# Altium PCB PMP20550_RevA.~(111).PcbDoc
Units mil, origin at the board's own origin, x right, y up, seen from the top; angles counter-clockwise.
Board outline 1966.66 x 1968.77 mil, 4 copper layers (Top Layer, POWER, GNDS, Bottom Layer), stack 79.834 mil thick; 56 components, 23 nets, 134 pads, 84 vias.
Unrouted connection lines stored in the file: 1.
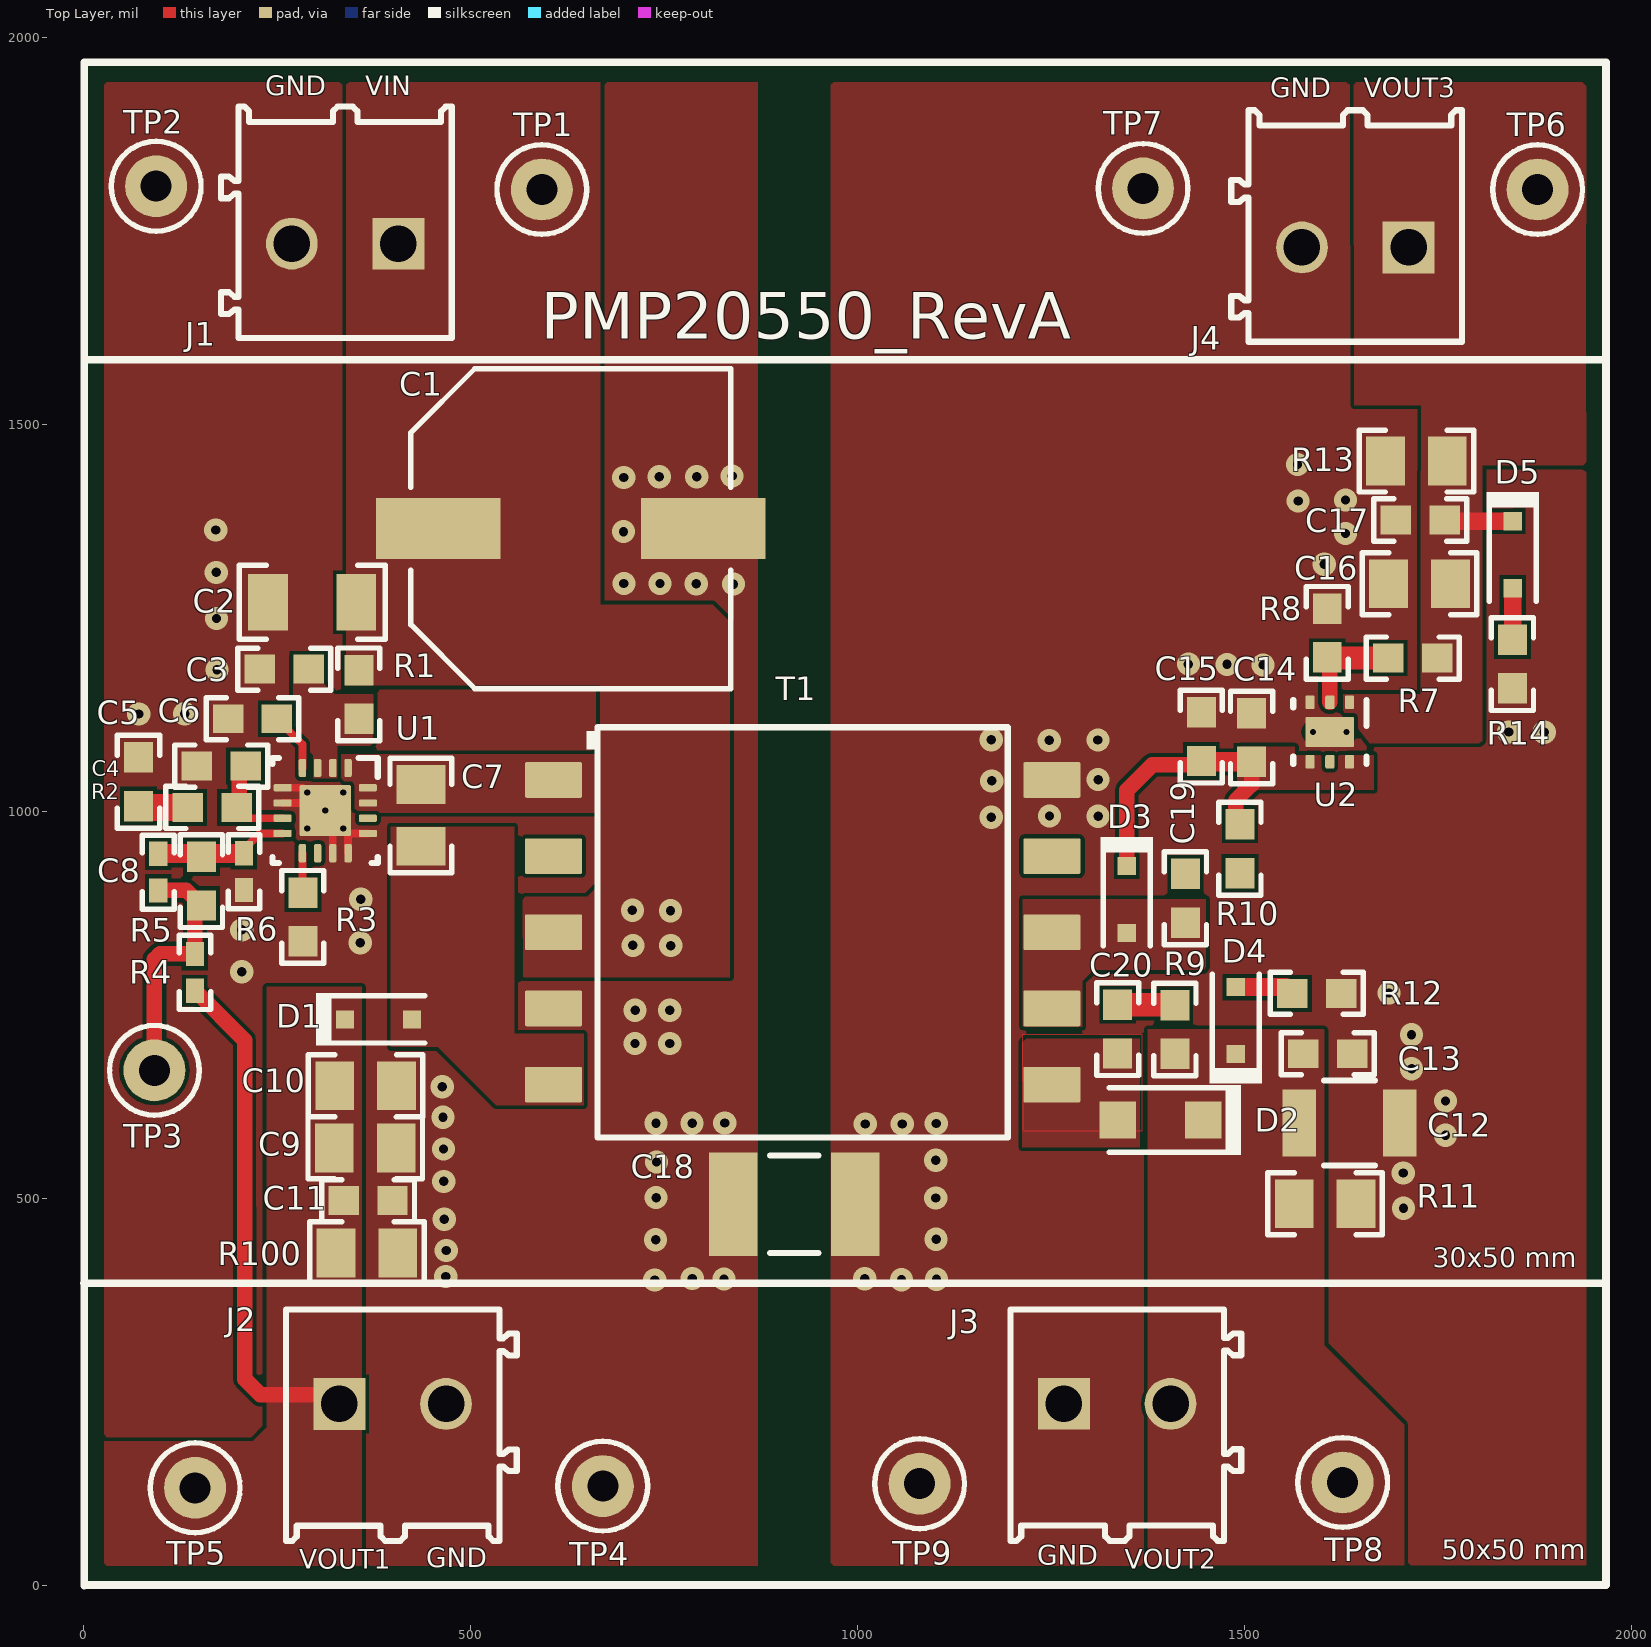
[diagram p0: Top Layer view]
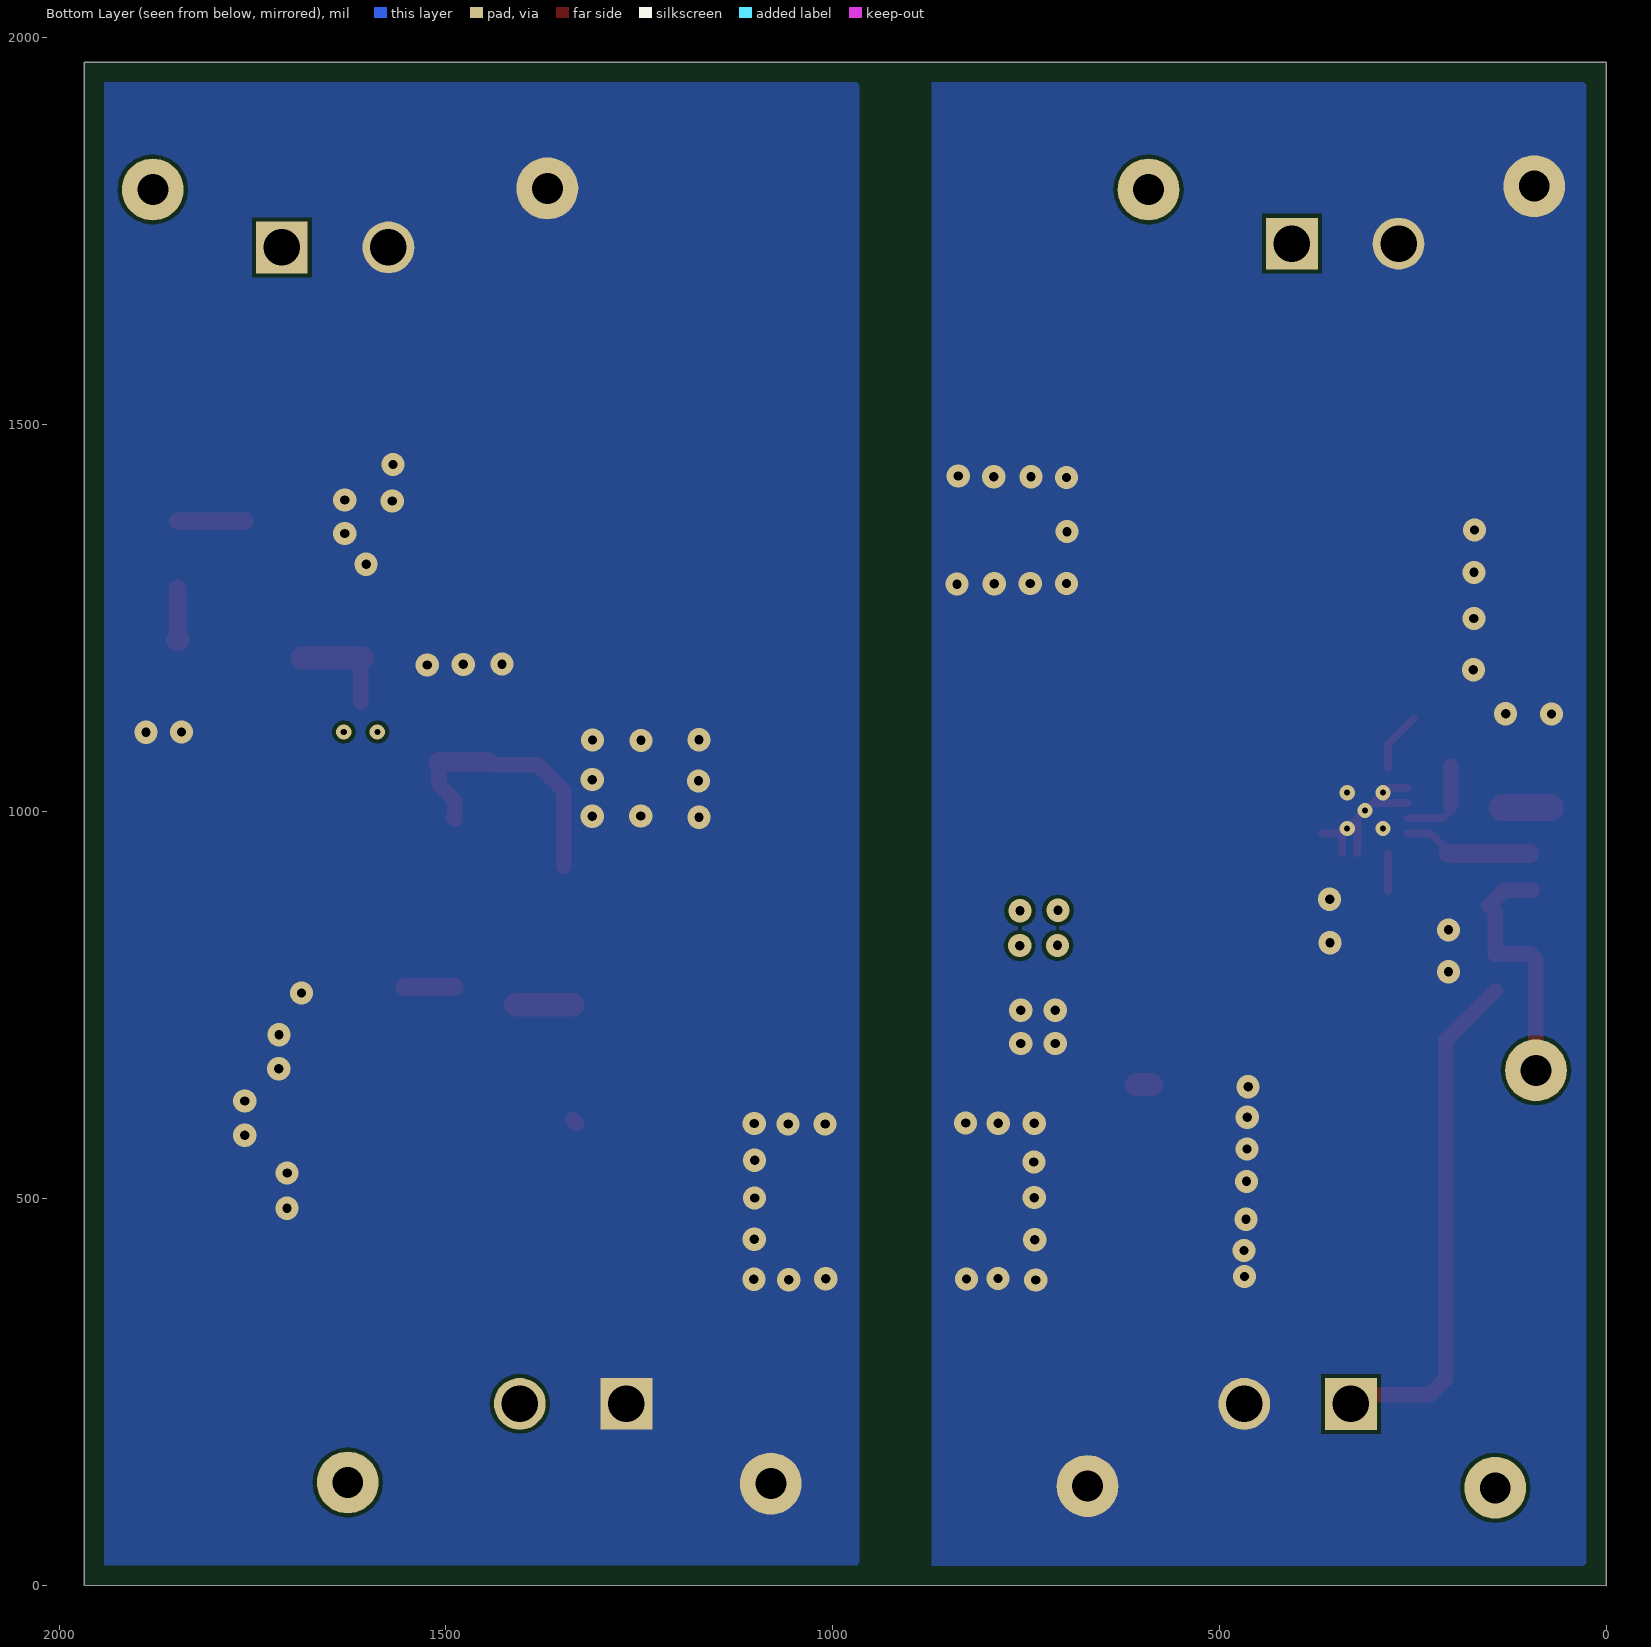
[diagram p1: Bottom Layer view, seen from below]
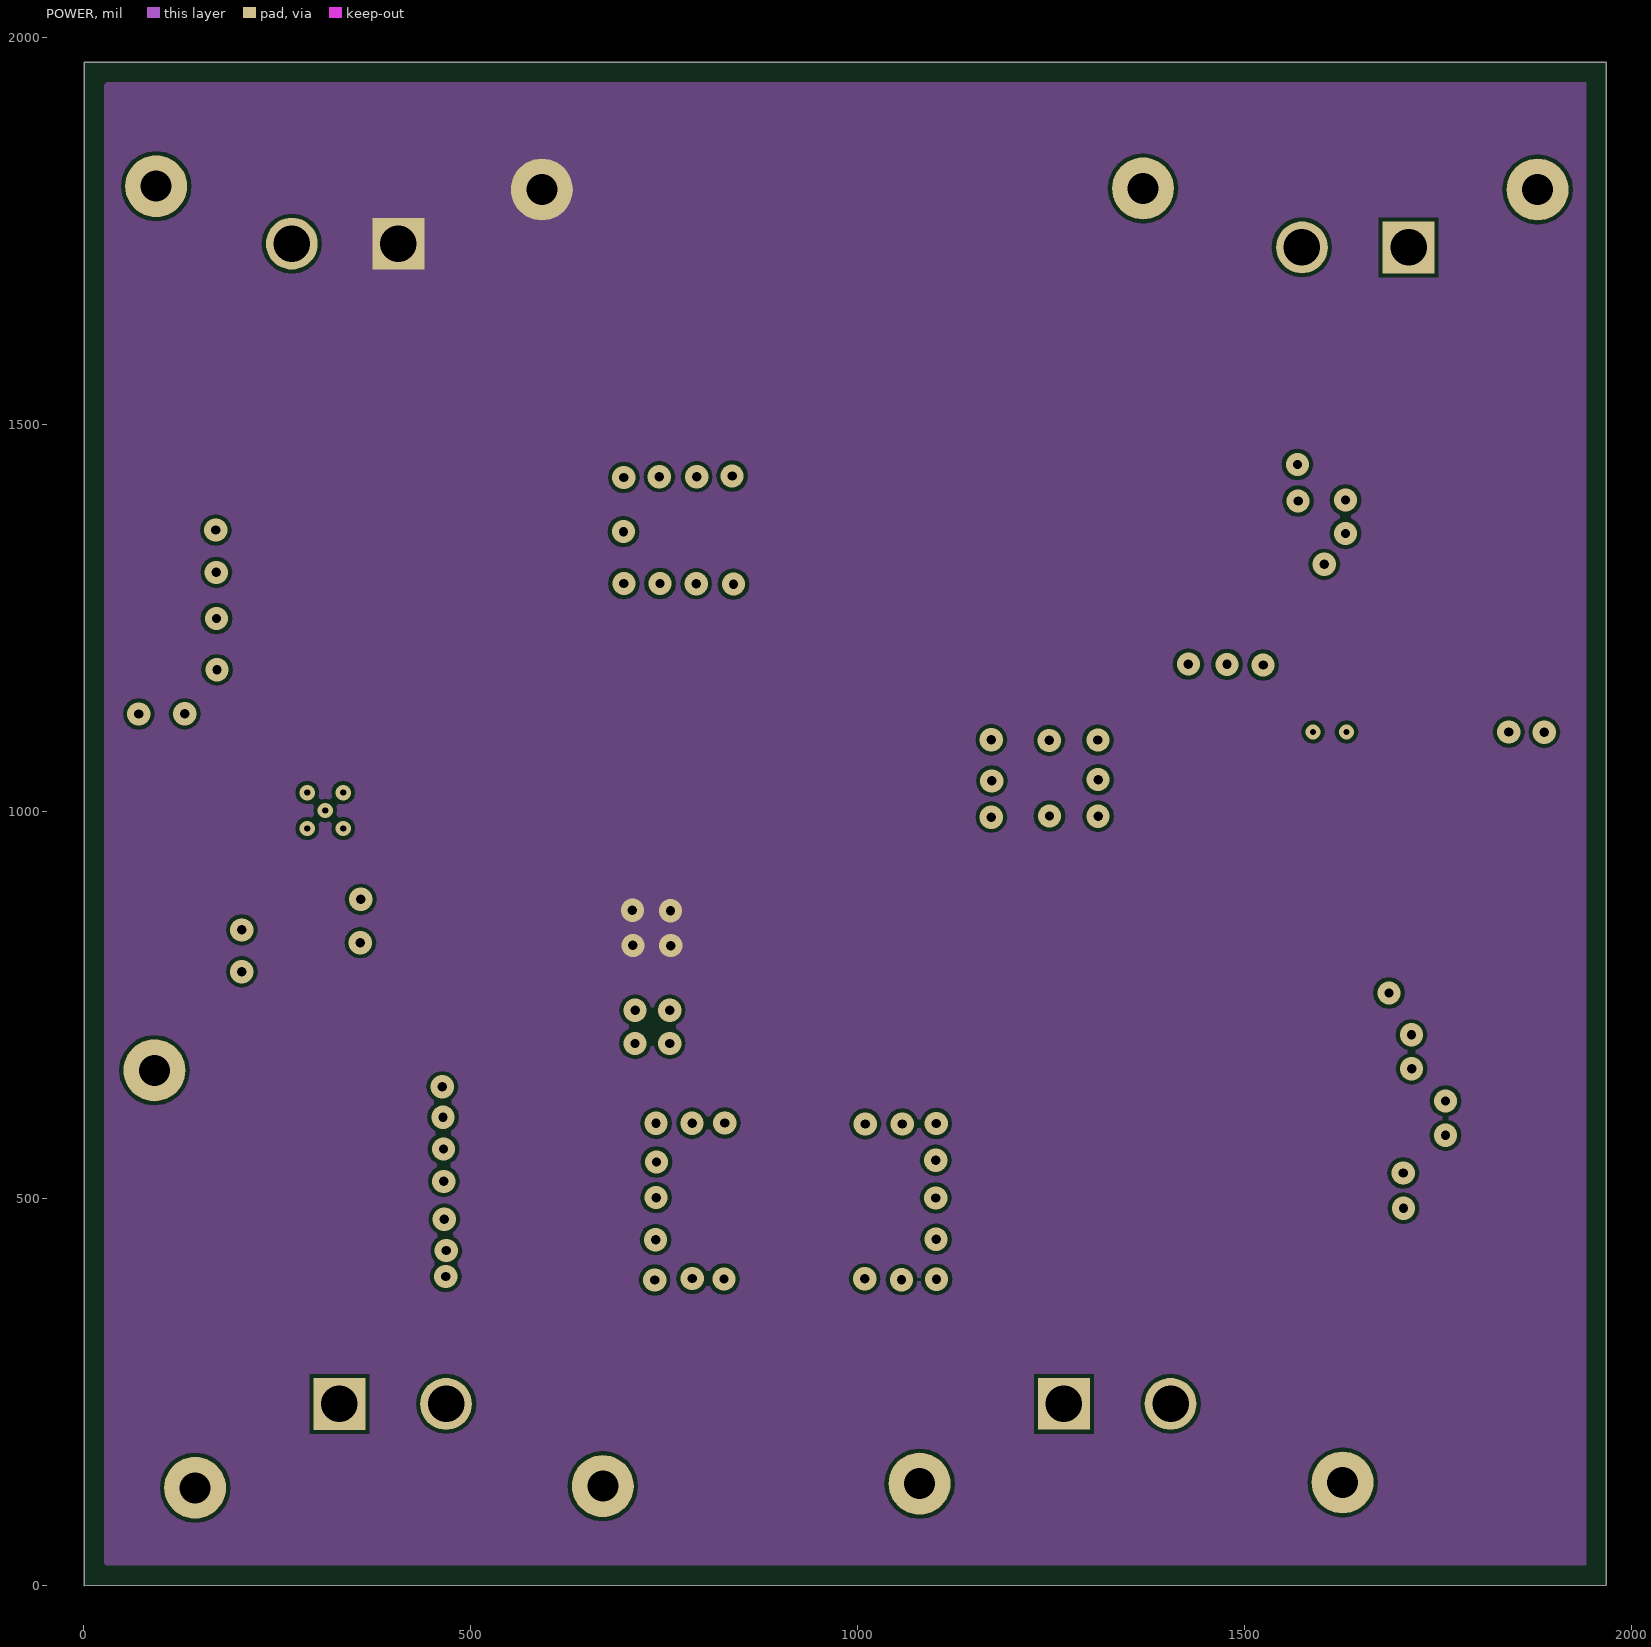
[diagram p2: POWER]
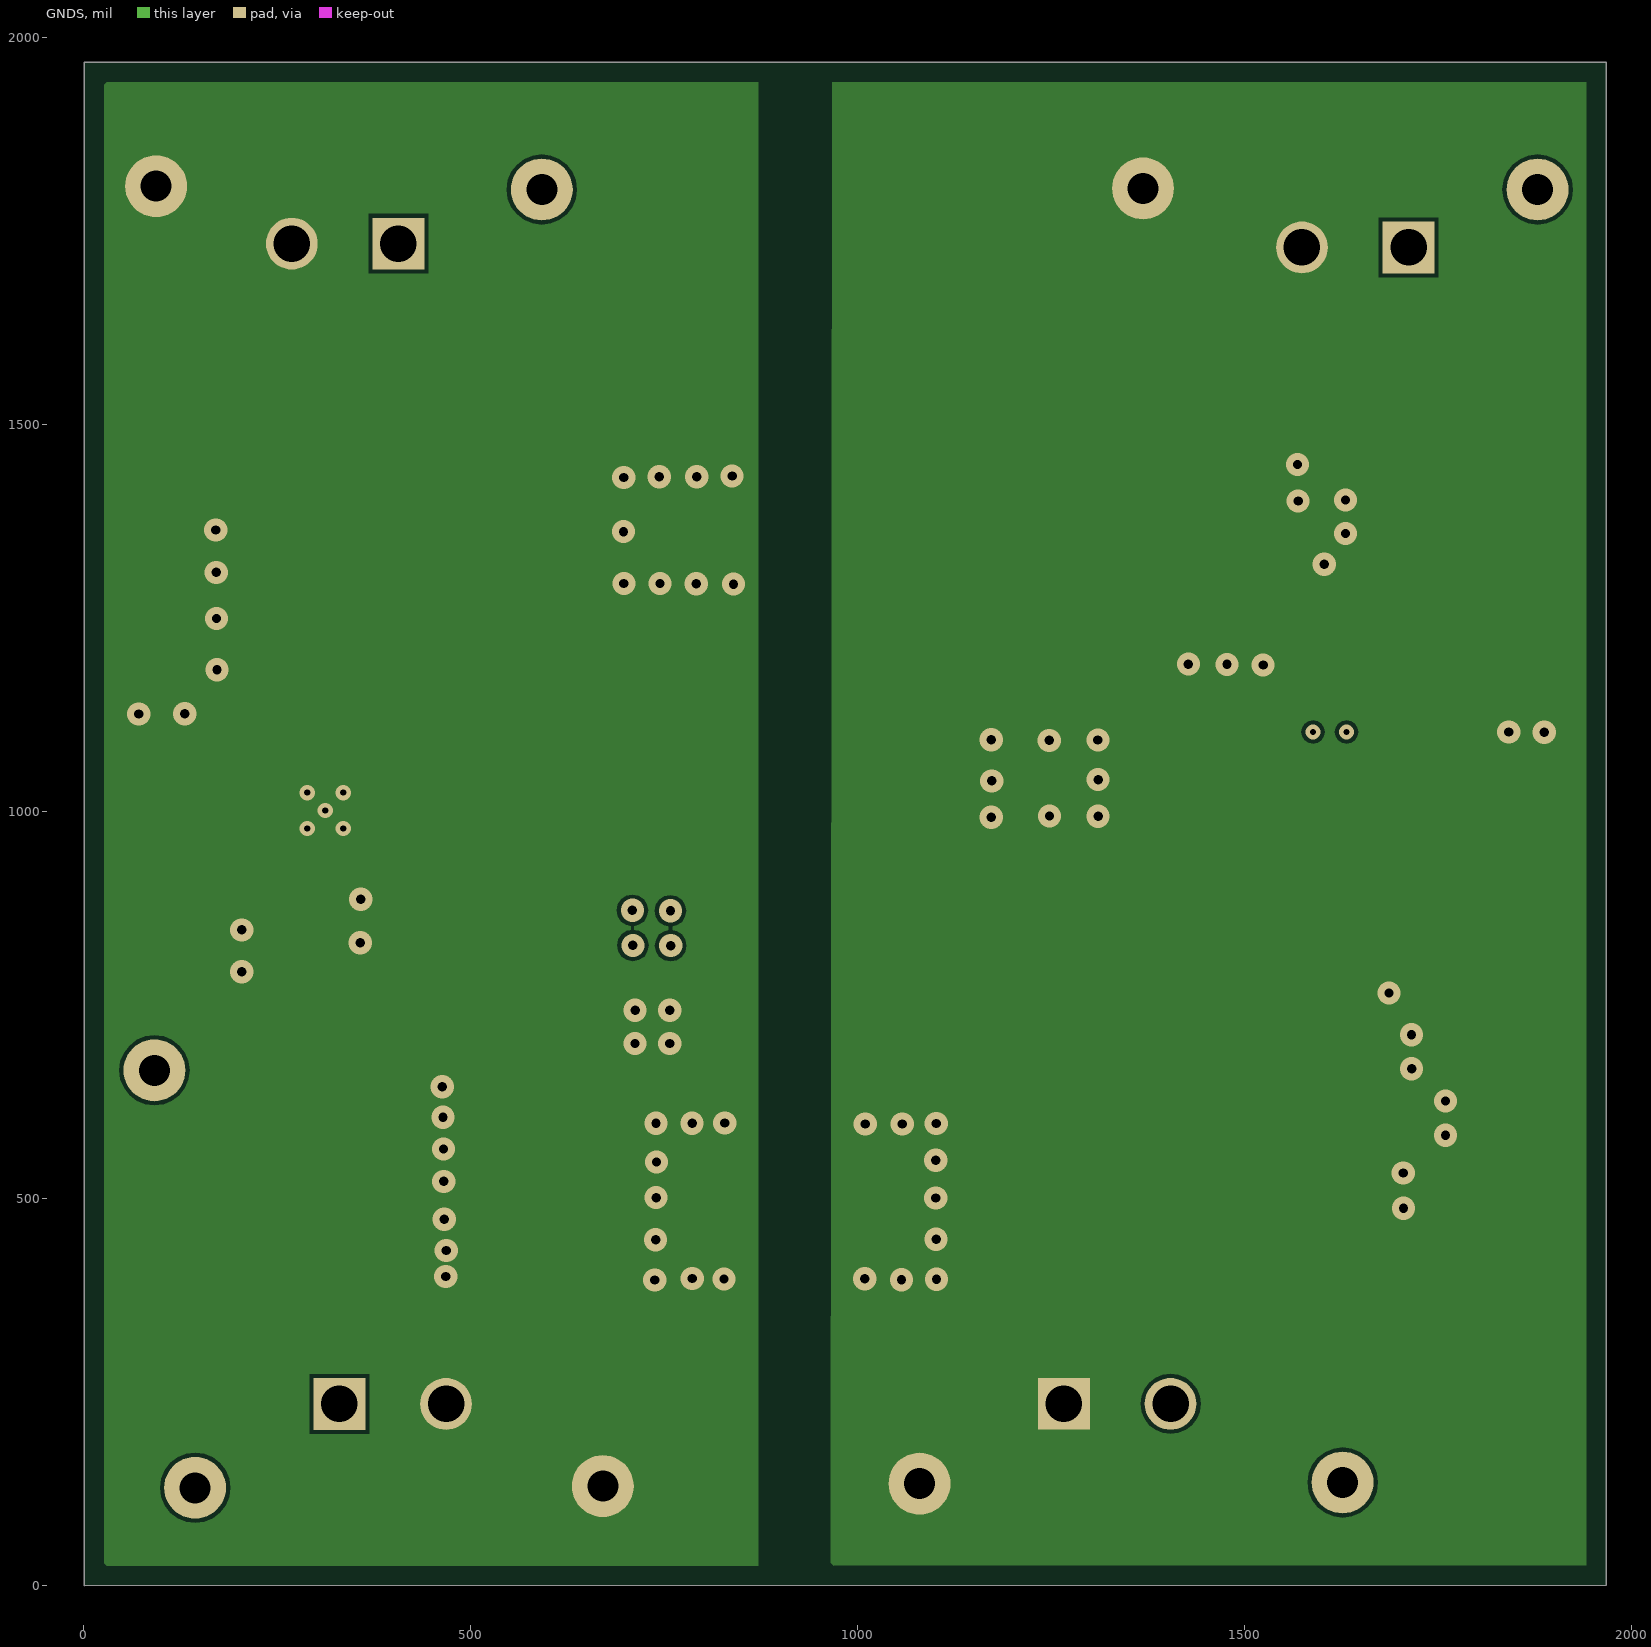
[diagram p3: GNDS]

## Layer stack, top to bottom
Top Solder: solder mask 0.4, Solder Resist, Dk 3.5
Top Layer: signal copper 1.4
Dielectric1: core 59.2, FR-4, Dk 4.8
POWER: signal copper 1.417
Dielectric 3: prepreg 5, Dk 4.2
GNDS: signal copper 1.417
Dielectric 2: core 10, Dk 4.2
Bottom Layer: signal copper 1.4
Bottom Solder: solder mask 0.4, Solder Resist, Dk 3.5

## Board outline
0.76,-0.43 0.76,1968.34 0.81,1968.29 1967.33,1968.29 1967.42,1968.2 1967.42,0.32 1967.36,0.38

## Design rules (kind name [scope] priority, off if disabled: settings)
AcuteAngle [All] p1: minimum=4.50000000000000E+0001 checktracksonly=FALSE
AssemblyTestPointUsage [All] p1: valid=2
BoardOutlineClearance BoardOutlineClearance_MountingHoles [OnCopper and InComponentClass('Mounting Holes')] p1: gap=40
BoardOutlineClearance BoardOutlineClearance_Poly [OnCopper and IsPoly] p2: gap=25
BoardOutlineClearance [OnCopper and Not InComponentClass('Logo') and not InComponentClass('FiducialMark') and not InRegion(1000,500,4000,800) and not InPoly] p3: gap=40
Clearance Clearance_3 [All] p1: gap=5
Clearance Clearance_2 [InNet('NetC1_1') vs InNetClass('Undefined')] p2: gap=80
Clearance Clearance_1 [InNet('GND') vs InNet('GND2')] p3: gap=80
Clearance Clearance_Keepouts [((IsTrack Or IsArc) And Not InPoly) And IsFree and IsKeepOut vs ((IsTrack Or IsArc) And Not InPoly) And IsFree and IsKeepOut] p4: gap=0
Clearance Clearance_Poly [InPolygon] p5: gap=10
Clearance [InNet('GND2') vs InNet('GND2')] p6: gap=0
ComponentClearance ComponentClearance_MountingHoles_FiducialMarks [InComponentClass('Mounting Holes') vs InComponentClass('FiducialMark')] p1: gap=50 collisioncheckmode=3 verticalgap=10 showdistances=FALSE
ComponentClearance ComponentClearance_Shunt [InComponentClass('Header') vs InComponentClass('Shunt')] p2: gap=0 collisioncheckmode=3 verticalgap=0 showdistances=FALSE
ComponentClearance ComponentClearance_Logo [InComponentClass('Logo')] p3: gap=50 collisioncheckmode=3 verticalgap=10 showdistances=FALSE
ComponentClearance ComponentClearance_ScrewToNut [(HasFootprint('NY PMS 440 0025 PH')) vs (HasFootprint('Keystone_1902C'))] p4: gap=5 collisioncheckmode=3 verticalgap=10 showdistances=FALSE
ComponentClearance ComponentClearance_MountingHoles [InComponentClass('Mounting Holes')] p5: gap=250 collisioncheckmode=3 verticalgap=100000 showdistances=FALSE
ComponentClearance ComponentClearance_SmallPassives [HasFootprint('0201*') or HasFootprint('0402*') or HasFootprint('0508') or HasFootprint('0603*') or HasFootprint('0612') or HasFootprint('0805*') or HasFootprint('0815*') or HasFootprint('0830*') or HasFootprint('1206*') or HasFootprint('1210*') or HasFootprint('1808*') or HasFootprint('1812*') or HasFootprint('1825*') or HasFootprint('2010*') or HasFootprint('2220*') or HasFootprint('2225*') or HasFootprint('2512*') or HasFootprint('2728*') or HasFootprint('3518*') vs HasFootprint('0201*') or HasFootprint('0402*') or HasFootprint('0508') or HasFootprint('0603*') or HasFootprint('0612') or HasFootprint('0805*') or HasFootprint('0815*') or HasFootprint('0830*') or HasFootprint('1206*') or HasFootprint('1210*') or HasFootprint('1808*') or HasFootprint('1812*') or HasFootprint('1825*') or HasFootprint('2010*') or HasFootprint('2220*') or HasFootprint('2225*') or HasFootprint('2512*') or HasFootprint('2728*') or HasFootprint('3518*')] p6: gap=14.96 collisioncheckmode=3 verticalgap=10 showdistances=FALSE
ComponentClearance ComponentClearance_THtoSMT [IsThruComponent vs IsSMTComponent] p7: gap=40 collisioncheckmode=3 verticalgap=30 showdistances=FALSE
ComponentClearance ComponentClearance_THtoTH [IsThruComponent vs IsThruComponent] p8: gap=30 collisioncheckmode=3 verticalgap=30 showdistances=FALSE
ComponentClearance [All] p9: gap=30 collisioncheckmode=3 verticalgap=10 showdistances=FALSE
DiffPairsRouting [All] p1: maxlimit=100 minlimit=10 mostfreqgap=10 toplayer_minwidth=15 toplayer_maxwidth=15 toplayer_prefwidth=15 midlayer1_minwidth=15 midlayer1_maxwidth=15 midlayer1_prefwidth=15 midlayer2_minwidth=15 midlayer2_maxwidth=15 midlayer2_prefwidth=15 bottomlayer_minwidth=15 bottomlayer_maxwidth=15 bottomlayer_prefwidth=15 maxuncoupledlength=1000
FabricationTestPointUsage TestPointUsage [All] p1: valid=2 allowmultiple=FALSE
FabricationTestpoint Testpoint [All] p1: side=3 testpointundercomponent=TRUE minsize=40 maxsize=100 preferedsize=60 minholesize=0 maxholesize=40 preferedholesize=32 testpointgrid=1 allowsidetop=TRUE allowsidebottom=TRUE usegrid=TRUE gridtolerance=0.01
FanoutControl Fanout_LCC [IsLCC] p1: bgadir=Out bgaviamode=Centered fanoutstyle=Auto fanoutdirection=Alternating viagrid=1 // Fanout_LCC (Default Rule)
FanoutControl Fanout_BGA [IsBGA] p2: bgadir=Out bgaviamode=Centered fanoutstyle=Auto fanoutdirection=Alternating viagrid=1 // Fanout_BGA (Default Rule)
FanoutControl Fanout_Default [All] p4: bgadir=Out bgaviamode=Centered fanoutstyle=Auto fanoutdirection=Alternating viagrid=1 // Fanout_Default (Default Rule)
FanoutControl Fanout_Small [(CompPinCount < 5)] p5: bgadir=Out bgaviamode=Centered fanoutstyle=Auto fanoutdirection=OutThenIn viagrid=1 // Fanout_Small (Default Rule)
HoleSize [All] p1: absolutevalues=TRUE maxlimit=251 minlimit=7.87 maxpercent=80.000 minpercent=20.000
MinimumAnnularRing MinimumAnnularRing_ThermalPadVias [IsVia and InAnyComponent] p1: minimumring=5.91
MinimumAnnularRing [All] p2: minimumring=8
MinimumSolderMaskSliver MinimumSolderMaskSliver_Logo [InComponentClass('Logo') vs InComponentClass('Logo')] p1: minsoldermaskwidth=0.7
MinimumSolderMaskSliver [All] p2: minsoldermaskwidth=3.94
PlaneConnect [All] p1: planeconnectstyle=Direct reliefexpansion=10 reliefentries=4 reliefconductorwidth=10 reliefairgap=10
PolygonConnect [All] p1: connectstyle=Direct reliefconductorwidth=10 reliefentries=4 polygonreliefangle="90 Angle" airgapwidth=10
RoutingVias ThermalPadVias [IsVia and InAnyComponent] p1: holewidth=7.87 width=19.68 viastyle="Through Hole" minholewidth=7.87 minwidth=19.68 maxholewidth=12.99 maxwidth=23.62
RoutingVias [All] p2: holewidth=16 width=34 viastyle="Through Hole" minholewidth=7.87 minwidth=26 maxholewidth=40 maxwidth=65
SilkToBoardRegionClearance [Not ((IsComment or IsDesignator) And (Hide <> 'False')) and not InRegion(1000,500,4000,800)] p1:
SilkToSilkClearance SilkToSilkClearance_Pb-FreeLogo [(HasFootprint('Pb-Free_Overlay_Medium') OR HasFootprint('Pb-Free_Overlay_Small')) vs (HasFootprint('Pb-Free_Overlay_Medium') OR HasFootprint('Pb-Free_Overlay_Small'))] p1: silktosilkclearance=0
SilkToSilkClearance [All] p2: silktosilkclearance=0
SilkToSolderMaskClearance SilkToComponentPadClearance [IsPad and InAnycomponent] p1: minsilkscreentomaskgap=4 clearancetoexposedcopper=TRUE
SilkToSolderMaskClearance "Silk to Solder Mask Opening" [All] p2: minsilkscreentomaskgap=0 clearancetoexposedcopper=FALSE
SolderMaskExpansion [All] p1: expansion=1.97
Width [All] p1: maxlimit=100 minlimit=6 preferedwidth=10 checkconnectedcopper=TRUE
15 further rules are at their usual default settings.

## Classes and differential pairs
net class Undefined: GND2 NetC12_1 NetC14_1 NetC16_1 NetC19_1 NetC20_1 NetC20_2 NetD4_2 NetD5_2 NetR7_1

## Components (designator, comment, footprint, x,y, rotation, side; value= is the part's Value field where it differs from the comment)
C1 "EEE-FC1V221P" SM_RADIAL_G 629.36,1365.64 r0 top
C2 "GMK316AB7106KL" 1206 295.27,1270.61 r180 top
C3 "C1608X7R1E104K080AA" 0603 259.1,1184.09 r180 top
C4 "CGA3E2NP01H101J080AA" 0603 177.65,1058.89 r180 top
C5 "UMK107AB7105KA-T" 0603 70.82,1038.63 r90 top
C6 "C1608X7R1E104K080AA" 0603 218.14,1119.95 r180 top
C7 "GRM21BR6YA106KE43L" 0805_HV 435.84,995.13 r90 top
C8 "GRM1555C1H201JA01D" 0402 96.31,921.67 r90 top
C9 "GRM21BZ71A226ME15L" 0805_HV 363.79,565.25 r0 top
C10 "GRM21BZ71A226ME15L" 0805_HV 364.32,645.64 r0 top
C11 "C0603X104K8RACTU" 0603 367.54,497.19 r0 top
C12 "12103D226MAT2A" 1210_280 1635.8,597.58 r0 top
C13 "GRM188R71H104KA93D" 0603 1607.68,687.06 r0 top
C14 "GRM188Z71A106MA73D" 0603 1509.32,1095.78 r90 top
C15 "C1608X7R1E104K080AA" 0603 1444.34,1096.88 r90 top
C16 "C2012X7R1E474K125AA" 0805_HV 1726.38,1294.41 r180 top
C17 "C0603X104K8RACTU" 0603 1727.27,1376.89 r180 top
C18 "GR443QR73D102KW01L" 1812 918.24,492.28 r180 top
C19 "GRM1885C1H182JA01D" 0603 1423.82,887.88 r270 top
C20 "GRM1885C1H111JA01D" 0603 1336.26,718.86 r270 top
D1 "PMEG2020EJ,115" SOD-323F 380.91,731.37 r0 top
D2 "PMEG10020ELRX" SOD-123W 1391.56,601.44 r180 top
D3 "PMEG2020EJ,115" SOD-323F 1348.01,886.28 r270 top
D4 "MMSZ5235BS-7-F" SOD-323 1488.8,729.89 r90 top
D5 "MMSZ5235BS-7-F" SOD-323 1846.77,1332.01 r270 top
J1 "1984617" Phoenix_1984617 337.81,1733.95 r180 top
J2 "1984617" Phoenix_1984617 399.35,234.48 r0 top
J3 "1984617" Phoenix_1984617 1335.67,234.61 r0 top
J4 "1984617" Phoenix_1984617 1643.31,1729.21 r180 top
R1 "ERJ-3GEY0R00V" 0603 355.63,1151.46 r90 top
R2 "RT0603BRB071KL" 0603 165.98,1005.32 r0 top
R3 "CRCW0603162KFKEA" 0603 283.22,863.89 r90 top
R4 "ERJ-2RKF49R9X" 0402 143.75,792.24 r270 top
R5 "CRCW060330K9FKEA" 0603 152.08,910.13 r270 top
R6 "ERJ-2RKF1002X" 0402 207.01,922.32 r90 top
R7 "RC0603FR-0778K7L" 0603 1717.69,1198.41 r0 top
R8 "RT0603DRE0724K3L" 0603 1607.13,1230.9 r270 top
R9 "CPF0603B1K62E" 0603 1410.31,718.37 r90 top
R10 "CRCW060340R2FKEA" 0603 1494.28,951.96 r90 top
R11 "ERJ-6ENF4871V" 0805_HV 1604.27,493.15 r180 top
R12 "CPF0603B1K62E" 0603 1593.62,765.04 r0 top
R13 "RT0805BRD071KL" 0805_HV 1722.29,1453.08 r0 top
R14 "CPF0603B1K62E" 0603 1846.38,1190.67 r270 top
R100 "RT0805BRD07499RL" 0805_HV 365.93,429.66 r180 top
T1 "750316553_Rev01" Wurth_750316553 929.2,844.01 r0 top
TP1 "5000" Keystone5000 592.04,1803.94 r90 top
TP2 "5001" Keystone5001 93.57,1808.22 r90 top
TP3 "5003" Keystone5003 91.35,665.59 r0 top
TP4 "5001" Keystone5001 670.84,128.24 r90 top
TP5 "VBUS" Keystone5000 143.95,126.09 r90 top
TP6 "5000" Keystone5000 1878.95,1803.95 r0 top
TP7 "5001" Keystone5001 1369.04,1805.37 r90 top
TP8 "5000" Keystone5000 1627,132.97 r0 top
TP9 "5001" Keystone5001 1080.24,131.4 r0 top
U1 "TPS55340QRTERQ1" RTE0016C 312.12,1001.24 r270 top
U2 "TPS79901QDRVRQ1" DRV0006A 1610.43,1102.85 r270 top

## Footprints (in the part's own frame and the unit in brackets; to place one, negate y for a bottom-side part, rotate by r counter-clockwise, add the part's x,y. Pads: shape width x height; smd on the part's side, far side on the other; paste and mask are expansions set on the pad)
0402 [mm] "0402 from SM-752 data"
  rect 0.8x0.6 smd: 1(-0.6,0) 2(0.6,0)
  silkscreen extent -1.22,-0.52 1.22,0.52, body extent -0.55,-0.3 0.55,0.3, height 0.6
0603 [mm] "0603 from SM-752 data"
  rect 1x0.95 smd: 1(-0.8,0) 2(0.8,0)
  silkscreen extent -1.52,-0.69 1.52,0.69, body extent -0.87,-0.47 0.87,0.47, height 1
0805_HV [mil] "0805 with 30mil clearance between pads"
  rect 50x63 smd: 1(-40,0) 2(40,0)
  silkscreen extent -74,-40 74,40, body extent -43,-29 43,29, height 57
1206 [mm] "1206 from SM-752 data"
  rect 1.3x1.85 smd: 1(-1.45,0) 2(1.45,0)
  silkscreen extent -2.4,-1.21 2.4,1.21, body extent -1.7,-0.9 1.7,0.9, height 1.35
1210_280 [mm] "SMD, 2-Leads, Body 3.6x2.8mm, Height 2.8mm"
  rect 1.1x2.2 smd: 1(-1.65,0) 2(1.65,0)
  silkscreen extent -0.84,-1.4 0.84,1.4, body extent -1.8,-1.4 1.8,1.4, height 2.8
1812 [mm]
  rect 1.6x3.4 smd: 1(-2,0) 2(2,0)
  silkscreen extent -0.8,-1.6 0.8,1.6, body extent -2.4,-1.7 2.4,1.7, height 1.35
DRV0006A [mm] "SON, 6-Leads, Body 2x2mm, Pitch 0.65mm, Thermal Pad 1.6x1mm, TI Recommended"
  rrect33% 0.45x0.3 smd: 1(-0.975,0.65) 2(-0.975,0) 3(-0.975,-0.65) 4(0.975,-0.65) 5(0.975,0) 6(0.975,0.65)
  rrect14% 1x0.7 on Top Paste: 7(0,0.45) 7(0,-0.45)
  rrect10% 1x1.6 smd paste-0.5: 7(0,0)
  silkscreen extent -1.05,-1.2 1.05,1.2, body extent -1.05,-1.05 1.05,1.05, height 0.81
Keystone5000 [mil] "For Keystone 500x miniature loop terminals"
  round 80 hole 40: 1(0,0)
  silkscreen extent -58,-58 58,58, body extent -49,-49 49,49, height 182
Keystone5001 [mil] "For Keystone 500x miniature loop terminals"
  round 80 hole 40: 1(0,0)
  silkscreen extent -58,-58 58,58, body extent -49,-49 49,49, height 182
Keystone5003 [mil] "For Keystone 500x miniature loop terminals"
  round 80 hole 40: 1(0,0)
  silkscreen extent -58,-58 58,58, body extent -49,-49 49,49, height 182
Phoenix_1984617 [mm] "Terminal Block, 3.5mm, 2x1, TH"
  rect 1.7x1.7 hole 1.2: 1(-1.75,0)
  round 1.7 hole 1.2: 2(1.75,0)
  silkscreen extent -3.5,-4.5 4.07,3.1, body extent -3.5,-4.5 4.07,3.1, height 9
RTE0016C [mm] "Texas Insturments"
  rrect42% 0.6x0.24 smd: 1(-1.4,0.75) 2(-1.4,0.25) 3(-1.4,-0.25) 4(-1.4,-0.75) 9(1.4,-0.75) 10(1.4,-0.25) 11(1.4,0.25) 12(1.4,0.75)
  rrect42% 0.24x0.6 smd: 5(-0.75,-1.4) 6(-0.25,-1.4) 7(0.25,-1.4) 8(0.75,-1.4) 13(0.75,1.4) 14(0.25,1.4) 15(-0.25,1.4) 16(-0.75,1.4)
  rrect6% 1.55x1.55 on Top Paste: 17(0,0)
  rrect6% 1.68x1.68 smd paste-0.85: 17(0,0)
  silkscreen extent -1.72,-1.73 1.72,1.73, body extent -1.57,-1.57 1.58,1.58, height 0.81
SM_RADIAL_G [mm] "10 x 10.2mm:  Panasonic G"
  rect 4.1x2 smd: 1(-4.35,0) 2(4.35,0)
  silkscreen extent -5.25,-5.25 5.25,5.25, body extent -5.25,-5.25 5.25,5.25, height 10.5
SOD-123W [mm] "NXP recommended land pattern"
  rect 1.2x1.2 smd paste-0.05: 1(-1.4,0) 2(1.4,0)
  silkscreen extent -2.64,-1.14 1.68,1.14, body extent -1.85,-0.95 1.85,0.95, height 1.1
SOD-323 [mm] "NXP recommended land pattern"
  rect 0.6x0.6 smd paste-0.05: 1(-1.1,0) 2(1.1,0)
  silkscreen extent -2.06,-0.86 1.53,0.86, body extent -1.3,-0.67 1.3,0.68, height 1.1
SOD-323F [mm] "NXP recommended land pattern"
  rect 0.6x0.6 smd paste-0.05: 1(-1.1,0) 2(1.1,0)
  silkscreen extent -2.06,-0.86 1.53,0.86, body extent -1.35,-0.67 1.35,0.68, height 0.79
Wurth_750316553 [mm] "SMD, 10-Leads, Body 17.75x13.46mm, Pitch 2.5mm"
  rrect9% 1.88x1.17 smd: 1(-8.18,5) 2(-8.18,2.5) 3(-8.18,0) 4(-8.18,-2.5) 5(-8.18,-5) 6(8.18,-5) 7(8.18,-2.5) 8(8.18,0) 9(8.18,2.5) 10(8.18,5)
  silkscreen extent -7.1,-6.73 6.73,6.73, body extent -8.87,-6.73 8.88,6.73, height 12.7

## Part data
C1: "CAP, AL, 220 µF, 35 V, +/- 20%, 0.15 ohm, SMD"
C2: "CAP, CERM, 10 µF, 35 V, +/- 10%, X7R, 1206"
C3 C6 C15: "CAP, CERM, 0.1 µF, 25 V, +/- 10%, X7R, 0603"
C4: "CAP, CERM, 100 pF, 50 V, +/- 5%, C0G/NP0, AEC-Q200 Grade 0, 0603"
C5: "CAP, CERM, 1 µF, 50 V, +/- 10%, X7R, 0603"
C7: "CAP, CERM, 10 µF, 35 V, +/- 10%, X5R, 0805"
C8: "CAP, CERM, 200 pF, 50 V, +/- 5%, C0G/NP0, 0402"
C9 C10: "CAP, CERM, 22 µF, 10 V, +/- 20%, X7R, 0805"
C11 C17: "CAP, CERM, 0.1 µF, 10 V, +/- 10%, X7R, 0603"
C12: "CAP, CERM, 22 µF, 25 V, +/- 20%, X5R, 1210"
C13: "CAP, CERM, 0.1 µF, 50 V, +/- 10%, X7R, 0603"
C14: "CAP, CERM, 10 µF, 10 V, +/- 20%, X7R, 0603"
C16: "CAP, CERM, 4.7 µF, 25 V, +/- 10%, X7R, 0805"
C18: "CAP, CERM, 1000 pF, 2000 V, +/- 10%, X7R, 1812"
C19: "CAP, CERM, 1800 pF, 50 V, +/- 5%, C0G/NP0, 0603"
C20: "CAP, CERM, 110 pF, 50 V, +/- 5%, C0G/NP0, 0603"
D1 D3: "Diode, Schottky, 20 V, 2 A, SOD-323F"
D2: "Diode, Schottky, 100 V, 2 A, AEC-Q101, SOD-123W"
D4 D5: "Diode, Zener, 6.8 V, 200 mW, SOD-323"
J1 J2 J3 J4: "Terminal Block, 3.5mm, 2x1, TH"
R1: "RES, 0, 5%, 0.1 W, 0603"
R2: "RES, 1.00 k, 0.1%, 0.1 W, 0603"
R3: "RES, 162 k, 1%, 0.1 W, 0603"
R4: "RES, 49.9, 1%, 0.1 W, AEC-Q200 Grade 0, 0402"
R5: "RES, 30.9 k, 1%, 0.1 W, 0603"
R6: "RES, 10.0 k, 1%, 0.1 W, 0402"
R7: "RES, 78.7 k, 1%, 0.1 W, 0603"
R8: "RES, 24.3 k, 0.5%, 0.1 W, 0603"
R9 R12 R14: "RES, 1.62 k, 0.1%, 0.063 W, 0603"
R10: "RES, 40.2, 1%, 0.1 W, 0603"
R11: "RES, 4.87 k, 1%, 0.125 W, 0805"
R13: "RES, 1.00 k, 0.1%, 0.125 W, 0805"
R100: "RES, 499, 0.1%, 0.125 W, 0805"
T1: library part 750316553, "Transformer, 52 uH, SMT"
TP1 TP6 TP8: "Test Point, Miniature, Red, TH"
TP2 TP4 TP7 TP9: "Test Point, Miniature, Black, TH"
TP3: "Test Point, Miniature, Orange, TH"
TP5: library part 5000, "Test Point, TH, Miniature, Red"
U1: "Integrated 5-A 40-V Wide Input Range Boost/SEPIC/Flyback DC-DC Regulator, RTE0016C"
U2: "Single Output High PSRR LDO, 200 mA, Adjustable 1.2 to 6.5 V Output, 2.7 to 6.5 V Input, with Low IQ, 6-pin SON (DRV), -40 to 125 degC, Green (RoHS & no Sb/Br)"

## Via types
v1: diameter 30, hole 12, Top Layer to Bottom Layer, tented top, 70 vias
v2: diameter 30, hole 12, Top Layer to Bottom Layer, 7 vias
v3: diameter 19.68, hole 7.87, Top Layer to Bottom Layer, tented top, 5 vias
v4: diameter 19.68, hole 7.87, Top Layer to Bottom Layer, 2 vias

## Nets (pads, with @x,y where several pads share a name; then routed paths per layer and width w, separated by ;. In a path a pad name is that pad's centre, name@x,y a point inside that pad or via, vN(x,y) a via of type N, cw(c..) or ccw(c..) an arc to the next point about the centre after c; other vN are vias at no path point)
GND: C1.2 C2.2 C3.2 C4.2 C5.2 C6.2 C9.2 C10.2 C11.2 C18.2 J1.2 J2.2 R3.1 R6.1 R100.1 T1.4 TP2.1 TP4.1 U1.5 U1.6 U1.11 U1.12 U1.13 U1.17@312.12,1001.24 | length 241.9
  Top Layer w10: U1.6 U1.17@302.28,1011.09 ; U1.5 U1.17@282.6,1030.77 ; v3(288.9,1024.47) U1.17@302.28,1011.09 ; U1.11 U1.17@321.97,991.4 ; U1.12 U1.17@341.65,971.72 ; U1.13 U1.17@341.65,971.72 ; U1.17@302.28,1011.09 v3(312.12,1001.24) U1.17@321.97,991.4 ; U1.17@321.97,991.4 U1.17@341.65,971.72
  other v1: 737.88,394.62 827.36,395.96 786.45,396.54 467.87,399.12 468.58,432.64 739.09,446.78 466,473.2 739.73,501.11 465.38,522.09 740.21,547.21 464.87,564.01 739.69,597.18 786.29,597.18 828.41,597.62 464.36,604.9 463.34,644.27 712.54,700.39 757.29,700.39 712.62,743.22 757.28,743.22 204.31,793 357.47,830.52 204.31,847.13 357.97,886.58 71.15,1126.18 130.55,1126.39 172.22,1183.22 171.54,1249.54 839.68,1293.98 698.06,1294.81 744.8,1294.81 791.55,1294.53 171.38,1309.15 697.5,1361.82 170.72,1363.82 697.99,1431.81 743.83,1432.79 792.14,1432.79 837.98,1433.78
  other v3: 288.9,978.02 335.35,978.02 335.35,1024.47
GND2: C12.2 C13.2 C14.2 C15.2 C16.2 C17.2 C18.1 J3.1 J4.2 R8.1 R11.1 R12.2 R13.1 R14.2 T1.10 TP7.1 TP9.1 U2.3 U2.7@1610.43,1102.85
  other v1: 1056.94,395.02 1009.28,396.19 1102.08,395.5 1101.6,447.37 1705.62,487.37 1101.12,500.67 1705.33,532.94 1101.14,549.41 1760.02,581.64 1010.03,596.37 1057.84,596.37 1101.71,596.86 1760.02,626.08 1716.15,667.66 1715.87,711.52 1686.82,765.64 1248.24,994.31 1311,993.97 1311,1041.29 1247.9,1092.04 1310.65,1092.39 1841.7,1102.86 1887.62,1102.52 1524.24,1189.38 1477.59,1190.24 1427.64,1190.58 1603.23,1319.57 1630.71,1359.51 1569.49,1401.49 1630.71,1402.74 1568.56,1448.64
  other v2: 1172.93,992.8 1173.58,1039.7 1172.93,1092.84
NetC1_1: C1.1 C2.1 J1.1 R1.2 T1.3 TP1.1
  other v2: 709.69,827.07 758.53,826.75 709.04,872.35 758.2,871.71
NetC3_1: C3.1 R1.1 U1.2 U1.3
NetC4_1: C4.1 R2.2 U1.7 | length 120.4
  Top Layer w10: R2.2@201.27,1009.12 R2.2 211.39,991.4 U1.7
  Top Layer w20: R2.2@201.27,1009.12 C4.1@201.27,1058.89
NetC5_1: C5.1 R2.1 | length 64.4
  Top Layer w20: C5.1 C5.1@72.63,1005.32
  Top Layer w35: C5.1@72.63,1005.32 R2.1
NetC6_1: C6.1 U1.4 | length 77.2
  Top Layer w10: C6.1 282.6,1086.99 U1.4
NetC7_1: C7.1 D1.2 T1.5 | length 19.1
  Top Layer w30: T1.5@588.1,647.16 T1.5
NetC7_2: C7.2 T1.1 U1.1 U1.15 U1.16
NetC8_1: C8.1 R4.1 R5.2 TP3.1 | length 329
  Top Layer w20: TP3.1 91.35,809.04 98.56,816.26 143.35,816.26 R4.1 143.75,870.3 R5.2 132.67,898.05 C8.1
NetC8_2: C8.2 R5.1 R6.2 U1.8 | length 181.8
  Top Layer w10: R6.2@198.61,943.01 227.31,971.72 U1.8
  Top Layer w20: 194.08,947.54 R6.2@198.61,943.01
  Top Layer w25: C8.2@99.61,945.84 R6.2@204.68,945.84
NetC9_1: C9.1 C10.1 C11.1 D1.1 J2.1 R4.2 R100.2 TP5.1 | length 664.3
  Top Layer w20: R4.2 207.9,704.47 208.07,266.55 228.31,246.31 318.62,246.31 J2.1
NetC12_1: C12.1 C13.1 D2.1 D4.1 J3.2 R9.1 R11.2 TP8.1
NetC14_1: C14.1 C15.1 D3.1 R10.2 U2.4 U2.6 | length 361.9
  Top Layer w20: D3.1 1348.01,1027.52 1381.05,1060.55 1439.51,1060.55 C15.1 C15.1@1445.44,1064.28 ; R10.2@1491.26,992.37 1488.76,989.87 1488.76,1014.3 1509.32,1034.86 C14.1@1509.32,1060.97
  Top Layer w25: C15.1@1445.44,1064.28 C14.1 C14.1@1509.32,1060.97
NetC16_1: C16.1 C17.1 D5.1 J4.1 R7.2 R13.2 TP6.1 U2.1 | length 88.7
  Top Layer w20: C17.1 C17.1@1760.34,1375.32
  Top Layer w23: C17.1@1760.34,1375.32 D5.1
NetC19_1: C19.1 R10.1
NetC19_2: C19.2 D3.2 T1.7 T1.8
NetC20_1: C20.1 R9.2 | length 74.3
  Top Layer w30: C20.1 1409.83,750.36 R9.2
NetC20_2: C20.2 D2.2 T1.6 | length 7.3
  Top Layer w20: D2.2@1331.26,596.25 D2.2
NetD4_2: D4.2 R12.1 | length 65.2
  Top Layer w23: D4.2 R12.1@1553.97,773.2
NetD5_2: D5.2 R14.1 | length 66.7
  Top Layer w23: R14.1@1846.77,1222.55 D5.2
  Top Layer w30: R14.1 R14.1@1846.77,1222.55
NetR3_2: R3.2 U1.9 | length 49.2
  Top Layer w10: U1.9 R3.2@282.65,896.93
NetR7_1: R7.1 R8.2 U2.2 | length 137.6
  Top Layer w20: R8.2 1608.12,1198.41 1610.43,1196.1 U2.2
  Top Layer w30: R8.2@1608.12,1198.41 R7.1
pads on no net: T1.2 T1.9 U1.10 U1.14 U1.17@312.12,1001.24 U2.5 U2.7@1592.71,1102.85 U2.7@1628.14,1102.85
copper on no net: | length 103920.8
  Top Layer w1: 9550.69,-159.95 9650.37,-60.27 9770.37,59.73 9890.37,179.73 10010.37,299.73 10130.37,419.73 10250.37,539.73 10370.37,659.73 10490.37,779.73 10610.37,899.73 10670.37,959.73 ; 9550.69,-99.95 9590.37,-60.27 9710.37,59.73 9830.37,179.73 9950.37,299.73 10070.37,419.73 10190.37,539.73 10310.37,659.73 10430.37,779.73 10550.37,899.73 10670.37,1019.73 ; 9550.69,-39.95 9650.37,59.73 9770.37,179.73 9890.37,299.73 10010.37,419.73 10130.37,539.73 10250.37,659.73 10370.37,779.73 10490.37,899.73 10610.37,1019.73 10670.37,1079.73 ; 9550.69,20.05 9590.37,59.73 9710.37,179.73 9830.37,299.73 9950.37,419.73 10070.37,539.73 10190.37,659.73 10310.37,779.73 10430.37,899.73 10550.37,1019.73 10670.37,1139.73 ; 9550.69,80.05 9650.37,179.73 9770.37,299.73 9890.37,419.73 10010.37,539.73 10130.37,659.73 10250.37,779.73 10370.37,899.73 10490.37,1019.73 10610.37,1139.73 ; 9550.69,140.05 9590.37,179.73 9710.37,299.73 9830.37,419.73 9950.37,539.73 10070.37,659.73 10190.37,779.73 10310.37,899.73 10430.37,1019.73 10550.37,1139.73 ; 9550.69,200.05 9650.37,299.73 9770.37,419.73 9890.37,539.73 10010.37,659.73 10130.37,779.73 10250.37,899.73 10370.37,1019.73 10490.37,1139.73 ; 9550.69,260.05 9590.37,299.73 9710.37,419.73 9830.37,539.73 9950.37,659.73 10070.37,779.73 10190.37,899.73 10310.37,1019.73 10430.37,1139.73 ; 9550.69,320.05 9650.37,419.73 9770.37,539.73 9890.37,659.73 10010.37,779.73 10130.37,899.73 10250.37,1019.73 10370.37,1139.73 ; 9550.69,380.05 9590.37,419.73 9710.37,539.73 9830.37,659.73 9950.37,779.73 10070.37,899.73 10190.37,1019.73 10310.37,1139.73 ; 9550.69,440.05 9650.37,539.73 9770.37,659.73 9890.37,779.73 10010.37,899.73 10130.37,1019.73 10250.37,1139.73 ; 9550.69,500.05 9590.37,539.73 9710.37,659.73 9830.37,779.73 9950.37,899.73 10070.37,1019.73 10190.37,1139.73 ; 9550.69,560.05 9650.37,659.73 9770.37,779.73 9890.37,899.73 10010.37,1019.73 10130.37,1139.73 ; 9550.69,620.05 9590.37,659.73 9710.37,779.73 9830.37,899.73 9950.37,1019.73 10070.37,1139.73 ; 9550.69,680.05 9650.37,779.73 9770.37,899.73 9890.37,1019.73 10010.37,1139.73 ; 9550.69,740.05 9590.37,779.73 9710.37,899.73 9830.37,1019.73 9950.37,1139.73 ; 9550.69,800.05 9650.37,899.73 9770.37,1019.73 9890.37,1139.73 ; 9550.69,860.05 9590.37,899.73 9710.37,1019.73 9830.37,1139.73 ; 9550.69,920.05 9650.37,1019.73 9770.37,1139.73 ; 9550.69,980.05 9590.37,1019.73 9710.37,1139.73 ; 9550.69,1040.05 9650.37,1139.73 ; 9550.69,1100.05 9590.37,1139.73 ; 9590.37,-180.27 9710.37,-60.27 9830.37,59.73 9950.37,179.73 10070.37,299.73 10190.37,419.73 10310.37,539.73 10430.37,659.73 10550.37,779.73 10670.37,899.73 ; 9650.37,-180.27 9770.37,-60.27 9890.37,59.73 10010.37,179.73 10130.37,299.73 10250.37,419.73 10370.37,539.73 10490.37,659.73 10610.37,779.73 10670.37,839.73 ; 9710.37,-180.27 9830.37,-60.27 9950.37,59.73 10070.37,179.73 10190.37,299.73 10310.37,419.73 10430.37,539.73 10550.37,659.73 10670.37,779.73 ; 9770.37,-180.27 9890.37,-60.27 10010.37,59.73 10130.37,179.73 10250.37,299.73 10370.37,419.73 10490.37,539.73 10610.37,659.73 10670.37,719.73 ; 9830.37,-180.27 9950.37,-60.27 10070.37,59.73 10190.37,179.73 10310.37,299.73 10430.37,419.73 10550.37,539.73 10670.37,659.73 ; 9890.37,-180.27 10010.37,-60.27 10130.37,59.73 10250.37,179.73 10370.37,299.73 10490.37,419.73 10610.37,539.73 10670.37,599.73 ; 9950.37,-180.27 10070.37,-60.27 10190.37,59.73 10310.37,179.73 10430.37,299.73 10550.37,419.73 10670.37,539.73 ; 10010.37,-180.27 10130.37,-60.27 10250.37,59.73 10370.37,179.73 10490.37,299.73 10610.37,419.73 10670.37,479.73 ; 10070.37,-180.27 10190.37,-60.27 10310.37,59.73 10430.37,179.73 10550.37,299.73 10670.37,419.73 ; 10130.37,-180.27 10250.37,-60.27 10370.37,59.73 10490.37,179.73 10610.37,299.73 10670.37,359.73 ; 10190.37,-180.27 10310.37,-60.27 10430.37,59.73 10550.37,179.73 10670.37,299.73 ; 10250.37,-180.27 10370.37,-60.27 10490.37,59.73 10610.37,179.73 10670.37,239.73 ; 10310.37,-180.27 10430.37,-60.27 10550.37,59.73 10670.37,179.73 ; 10370.37,-180.27 10490.37,-60.27 10610.37,59.73 10670.37,119.73 ; 10430.37,-180.27 10550.37,-60.27 10670.37,59.73 ; 10490.37,-180.27 10610.37,-60.27 10670.37,-0.27 ; 10550.37,-180.27 10670.37,-60.27 ; 10610.37,-180.27 10670.37,-120.27
  Top Layer w15: 6131.57,-60.27 6541.48,-60.27 7471.23,-60.27 8330.99,-60.27 8980.83,-60.27 9550.69,-60.27 10670.37,-60.27 ; 6131.57,59.73 6541.48,59.73 7471.23,59.73 8330.99,59.73 8980.83,59.73 9550.69,59.73 10670.37,59.73 ; 6131.57,179.73 6541.48,179.73 7471.23,179.73 8330.99,179.73 8980.83,179.73 9550.69,179.73 10670.37,179.73 ; 6131.57,299.73 6541.48,299.73 7471.23,299.73 8330.99,299.73 8980.83,299.73 9550.69,299.73 10670.37,299.73 ; 6131.57,419.73 6541.48,419.73 7471.23,419.73 8330.99,419.73 8980.83,419.73 9550.69,419.73 10670.37,419.73 ; 6131.57,539.73 6541.48,539.73 7471.23,539.73 8330.99,539.73 8980.83,539.73 9550.69,539.73 10670.37,539.73 ; 6131.57,659.73 6541.48,659.73 7471.23,659.73 8330.99,659.73 8980.83,659.73 9550.69,659.73 10670.37,659.73 ; 6131.57,779.73 6541.48,779.73 7471.23,779.73 8330.99,779.73 8980.83,779.73 9550.69,779.73 10670.37,779.73 ; 6131.57,899.73 6541.48,899.73 7471.23,899.73 8330.99,899.73 8980.83,899.73 9550.69,899.73 10670.37,899.73 ; 6131.57,1019.73 6541.48,1019.73 7471.23,1019.73 8330.99,1019.73 8980.83,1019.73 9550.69,1019.73 10670.37,1019.73 ; 6131.57,1139.73 10670.37,1139.73 ; 6541.48,1259.73 6541.48,-180.27 ; 7471.23,1259.73 7471.23,-180.27 ; 8330.99,1259.73 8330.99,-180.27 ; 8980.83,1259.73 8980.83,-180.27 ; 9550.69,1259.73 9550.69,-180.27 ; 6541.48,-180.27 6131.57,-180.27 6131.57,1259.73 10670.37,1259.73 10670.37,-180.27 9550.69,-180.27 ; 6541.48,-180.27 7471.23,-180.27 ; 7471.23,-180.27 8330.99,-180.27 ; 8330.99,-180.27 8980.83,-180.27 ; 8980.83,-180.27 9550.69,-180.27
  other v4: 1588.77,1102.85 1632.08,1102.85

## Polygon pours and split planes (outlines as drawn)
NetC14_1 on Top Layer "Top Layer-No Net 13" (solid, pour order 16): 1490.63,1083.66 1565.23,1083.66 1565.23,1073.04 1582.28,1073.04 1667.14,1073.04 1667.14,1028.4 1490.88,1028.4
NetC20_2 on Top Layer "Top Layer-No Net 12" (solid, pour order 18): 1364.94,706.55 1214.01,706.68 1213.57,707.12 1212.99,706.55 1212.99,566.37 1364.94,566.37
NetC3_1 on Top Layer "Top Layer-No Net 4" (solid, pour order 42): 271.3,1202.21 270.6,1201.51 270.6,1097.93 296.64,1072.92 296.64,1043.16 315.48,1043.16 327.61,1043.16 327.61,1055.56 327.61,1085.23 374.08,1085.23 373.65,1101.6 374.31,1102.26 374.31,1151.46 324.21,1151.46 320.13,1155.55 309.59,1166.08 309.59,1202.55
NetC9_1 on Top Layer "Top Layer-No Net" (solid, pour order 48): 26.25,-2.6 26.25,186.05 218.59,186.05 237.25,204.71 236.31,205.65 236.31,773.3 359.56,773.3 359.56,25.31 421.08,-36.21
NetC7_2 on Top Layer "Top Layer-No Net 3" (solid, pour order 52): 330.27,1074.83 331.22,1073.88 661.33,1073.88 661.33,1042.72 661.33,998.74 335.74,998.74
NetC1_1 on Top Layer "Top Layer-No Net 5" (solid, pour order 54): 339.31,1944.8 339.31,1162.89 338.71,1162.29 339.37,1162.95 667.71,1162.95 667.71,1943.13 669.04,1944.45
NetC1_1 on Top Layer "Top Layer-No Net 6" (solid, pour order 58): 567.92,786.77 568.77,785.92 835.04,785.92 835.04,1245.17 815.11,1265.1 812.79,1267.42 667.45,1267.42 667.45,906.72 652.14,891.4 650.44,889.7 567.07,889.7
NetC16_1 on Top Layer "Top Layer-No Net 1" (solid, pour order 60): 1941.93,1942.72 1941.55,1943.09 1641.27,1943.09 1642.05,1525.47 1728.66,1525.47 1728.66,1440.4 1727.89,1439.63 1727.89,1151.93 1627.73,1151.93 1627.73,1130.46 1661.93,1088.51 1803.68,1088.51 1806,1086.19 1807.55,1087.74 1807.55,1446.59 1807.55,1447.36 1941.93,1447.36 1941.34,1581.15
NetC12_1 on Top Layer "Top Layer-No Net 8" (solid, pour order 64): 1375.13,718.42 1602.53,718.42 1603.46,717.48 1603.46,316.97 1603.46,310.42 1706.4,207.48 1706.4,10.97 1385.43,10.97 1375.13,21.26
NetC19_2 on Top Layer "Top Layer-No Net 2" (solid, pour order 66): 1213.82,886.63 1450.31,886.63 1450.31,794.24 1449.73,793.66 1447.98,795.41 1310.86,795.41 1305.05,795.41 1291.1,781.46 1290.52,780.88 1290.52,722.19 1214.41,722.19 1213.82,721.61
no net on Top Layer "Top Layer-No Net 9" (solid, pour order 68): 1213.55,712.03 1367.63,712.03 1367.63,586.74 1367.19,587.18 1213.96,587.18
NetC7_1 on Top Layer "Top Layer-No Net 7" (solid, pour order 20): 645.92,620.59 533,620.59 481.19,672.4 457.79,695.8 396.89,695.8 396.89,730.61 396.89,761.24 396.89,777.73 396.89,782.22 396.89,980.2 556.24,980.2 556.24,712.58 645.92,712.58
GND on Top Layer "Top Layer-No Net 10" (solid, pour order 70): 871.08,7.23 871.08,1963.51 5.59,1963.51 0.81,1968.29 0.76,1968.23 0.76,-0.43
GND2 on Top Layer "Top Layer-No Net 11" (solid, pour order 72): 965.74,4.81 965.74,1958.65 975.37,1968.29 1967.33,1968.29 1967.33,0.4 1967.42,0.32
NetC1_1 on POWER "POWER-No Net" (solid, pour order 28): 0.81,1968.29 0.9,1968.2 1967.42,1968.2 1967.42,0.32 1967.36,0.38 1.56,0.38
GND2 on GNDS "GND2" (solid, pour order 36): 965.46,0.2 1967.36,0.38 1967.36,1968.26 1963.66,1964.61 967.67,1964.61
GND on GNDS "GND1" (solid, pour order 34): 871.68,6.54 7.73,6.54 1.56,0.38 0.81,1.12 0.81,1968.29 871.68,1968.29
GND2 on Bottom Layer "bot - gnd2" (solid, pour order 46): 1969.72,1967.03 1965.01,1971.74 965.71,1971.74 965.71,7.87 1972.08,7.87
GND on Bottom Layer "bot - gnd1" (solid, pour order 44): 3.49,1967.03 872.33,1967.03 872.33,1914.05 872.33,5.51 8.21,5.51 1.13,-1.56

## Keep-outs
Keep-Out Layer:
  text ".Layer_Name" at 577,-858.49 h60

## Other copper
Top Layer:
  text "Layer" at 6191.57,1169.73 h60
  text "Name" at 6601.48,1169.73 h60
  text "Material" at 7531.23,1169.73 h60
  text "Thickness" at 8390.99,1169.73 h60
  text "Constant" at 9040.83,1169.73 h60
  text "Board Layer Stack" at 9610.69,1169.73 h60
  text "1" at 6191.57,1049.73 h60
  text "Top Overlay" at 6601.48,1049.73 h60
  text "2" at 6191.57,929.73 h60
  text "Top Solder" at 6601.48,929.73 h60
  text "Solder Resist" at 7531.23,929.73 h60
  text "0.40mil" at 8390.99,929.73 h60
  text "3.5" at 9040.83,929.73 h60
  text "3" at 6191.57,809.73 h60
  text "Top Layer" at 6601.48,809.73 h60
  text "Copper" at 7531.23,809.73 h60
  text "1.40mil" at 8390.99,809.73 h60
  text "4" at 6191.57,689.73 h60
  text "Dielectric1" at 6601.48,689.73 h60
  text "FR-4" at 7531.23,689.73 h60
  text "59.20mil" at 8390.99,689.73 h60
  text "4.8" at 9040.83,689.73 h60
  text "5" at 6191.57,569.73 h60
  text "POWER" at 6601.48,569.73 h60
  text "Copper" at 7531.23,569.73 h60
  text "1.42mil" at 8390.99,569.73 h60
  text "6" at 6191.57,449.73 h60
  text "Dielectric 3" at 6601.48,449.73 h60
  text "5.00mil" at 8390.99,449.73 h60
  text "4.2" at 9040.83,449.73 h60
  text "7" at 6191.57,329.73 h60
  text "GNDS" at 6601.48,329.73 h60
  text "Copper" at 7531.23,329.73 h60
  text "1.42mil" at 8390.99,329.73 h60
  text "8" at 6191.57,209.73 h60
  text "Dielectric 2" at 6601.48,209.73 h60
  text "10.00mil" at 8390.99,209.73 h60
  text "4.2" at 9040.83,209.73 h60
  text "9" at 6191.57,89.73 h60
  text "Bottom Layer" at 6601.48,89.73 h60
  text "Copper" at 7531.23,89.73 h60
  text "1.40mil" at 8390.99,89.73 h60
  text "10" at 6191.57,-30.27 h60
  text "Bottom Solder" at 6601.48,-30.27 h60
  text "Solder Resist" at 7531.23,-30.27 h60
  text "0.40mil" at 8390.99,-30.27 h60
  text "3.5" at 9040.83,-30.27 h60
  text "11" at 6191.57,-150.27 h60
  text "Bottom Overlay" at 6601.48,-150.27 h60
  text ".Layer_Name" at 577,-858.49 h60
Bottom Layer:
  text ".Layer_Name" at 577,-858.49 h60

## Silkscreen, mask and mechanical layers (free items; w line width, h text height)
Top Overlay:
  lines w10: 0.22,390.5 1967.38,390.5 ; 0.76,-0.43 0.76,1968.34 0.81,1968.29 1967.33,1968.29 1967.42,1968.2 1967.42,0.32 1967.36,0.38 1.56,0.38 ; 2.15,1583.98 1965.61,1583.98
  text "GND" at 234.8,1925.94 h25
  text "VIN" at 363.98,1926.01 h25
  text "GND" at 1533.71,1923.51 h25
  text "VOUT3" at 1654.35,1923.05 h25
  text "PMP20550_RevA" at 590.93,1611.16 h60
  text "30x50 mm" at 1743.5,410.95 h25
  text "50x50 mm" at 1755.09,33.73 h25
  text "GND" at 1232.3,26.61 h25
  text "GND" at 442.94,23.43 h25
  text "VOUT1" at 278.39,21.65 h25
  text "VOUT2" at 1345.21,21.76 h25
  text ".Layer_Name" at 577,-858.49 h60
Bottom Overlay:
  text ".Layer_Name" at 577,-858.49 h60
Top Paste:
  text ".Layer_Name" at 577,-858.49 h60
Bottom Paste:
  text ".Layer_Name" at 577,-858.49 h60
Top Solder:
  text ".Layer_Name" at 577,-858.49 h60
  text ".Layer_Name" at 577,-858.49 h60
Bottom Solder:
  text ".Layer_Name" at 577,-858.49 h60
Drill Guide:
  text ".Layer_Name" at 577,-858.49 h60
M1 Board Outline:
  text ".Layer_Name" at 577,-858.49 h60
M2 Board Dimensions:
  rectangle: 0,-275 125,-150
  rectangle: 125,-400 500,-275
  lines w7: 0,-275 1000,-275 ; 125,-400 125,-150 ; 250,-400 250,-150 ; 500,-400 500,-150 ; 750,-400 750,-150 ; 0,-400 1000,-400 1000,-150 0,-150 0,-400
  text ".Layer_Name" at 577,-858.49 h60
M3 3D STEP Top:
  text ".Layer_Name" at 577,-858.49 h60
M4 3D STEP Bottom:
  text ".Layer_Name" at 577,-858.49 h60
M5 Assembly Top:
  lines w10: -292,-930.17 6308,-930.17 ; -292,-726.83 6310,-726.83 ; -292,-523.5 -292,-1133.5 3713,-1133.5 6310,-1133.5 6310,-523.5 -291.5,-523.5 -291.5,-1133.5 1284,-1133.5 ; 2173,-1133.5 2173,-523.5 ; 3440,-726.83 3440,-523.5 ; 4280,-726.83 4280,-523.5 ; 4902,-1140 4902,-937.17
  text "COMPONENTS MARKED 'DNP' SHOULD NOT BE POPULATED." at 1153.5,-318.5 h60
  text "ASSEMBLY VARIANT:" at 1153,-434 h60
  text ".VariantName" at 2189,-434 h60
  text "PCB VIEWED FROM TOP SIDE" at -228.5,-655.67 h60
  text "BOARD #:" at 2248,-655.67 h60
  text ".PRJ_Number" at 2793.5,-655.67 h60
  text "REV:" at 3638,-655.67 h60
  text ".PCB_Rev" at 3929.5,-655.67 h60
  text "SVN REV:" at 4476,-655.67 h60
  text ".VersionControl_RevNumber" at 4982,-655.67 h60
  text "TID #:" at 2248,-859 h60
  text ".TID" at 2793.5,-859 h60
  text "PLOT NAME =" at -228.5,-1064.34 h60
  text ".plot_File_Name" at 577,-1064.34 h60
  text "GENERATED    :" at 2250,-1064.34 h60
  text ".Print_Date" at 3119.5,-1064.34 h60
  text ".Print_Time" at 3848.5,-1064.34 h60
  text "TEXAS INSTRUMENTS" at 5113,-1064.34 h60
M6 Assembly Bottom:
  lines w10: -292.5,-727.33 6309.5,-727.33 ; -290.5,-930.67 6309.5,-930.67 ; 1115.5,-1140.5 1115.5,-937.67 ; 1737.5,-727.33 1737.5,-524 ; 2577.5,-727.33 2577.5,-524 ; 3844.5,-1134 3844.5,-524 ; 4733.5,-1134 6309,-1134 6309,-524 -292.5,-524 -292.5,-1134 2304.5,-1134 6309.5,-1134 6309.5,-524
  text "COMPONENTS MARKED 'DNP' SHOULD NOT BE POPULATED." at 6102,-318 h60
  text ".VariantName" at 5058,-434 h60
  text "ASSEMBLY VARIANT:" at 6097,-434 h60
  text ".VersionControl_RevNumber" at 1035.5,-656.17 h60
  text "SVN REV:" at 1541.5,-656.17 h60
  text ".PCB_Rev" at 2088,-656.17 h60
  text "REV:" at 2379.5,-656.17 h60
  text ".PRJ_Number" at 3224,-656.17 h60
  text "BOARD #:" at 3769.5,-656.17 h60
  text "PCB VIEWED FROM BOTTOM SIDE" at 6246,-656.17 h60
  text ".TID" at 3224,-859.5 h60
  text "TID #:" at 3769.5,-859.5 h60
  text "TEXAS INSTRUMENTS" at 904.5,-1064.84 h60
  text ".Print_Time" at 2169,-1064.84 h60
  text ".Print_Date" at 2898,-1064.84 h60
  text "GENERATED    :" at 3767.5,-1064.84 h60
  text ".plot_File_Name" at 5440.5,-1064.84 h60
  text "PLOT NAME =" at 6246,-1064.84 h60
M9 Title Sheet:
  drawing of 57 lines, arcs and shapes, not listed
  text "1" at 739.84,8036.5 h70
  text "2" at 3235.5,8036.5 h70
  text "3" at 5724.84,8036.5 h70
  text "4" at 8231.51,8036.5 h70
  text "5" at 10730.5,8036.5 h70
  text "6" at 13235.5,8036.5 h70
  text "A" at -416.5,6893.5 h70
  text "A" at 14383.5,6893.5 h70
  text "B" at -416.5,4513.5 h70
  text "B" at 14383.5,4513.5 h70
  text "C" at -416.5,2138.5 h70
  text "C" at 14383.5,2138.5 h70
  text "PROJECT TITLE:" at 11343.5,277.5 h45
  text ".PRJ_Title" at 11393.5,144.17 h70
  text "DESIGNED FOR:" at 11343.5,-23.5 h45
  text ".PRJ_Customer" at 11393.5,-163.5 h70
  text "D" at -416.5,-231.5 h70
  text "D" at 14383.5,-231.5 h70
  text "FILE NAME:" at 11343.5,-323.5 h45
  text ".PCB_File_Name_No_Path" at 11393.5,-443.5 h70
  text "Texas Instruments (TI) and/or its licensors do not warrant the accuracy or completeness of this specification" at 6374,-605.34 h45
  text "ENGINEER:" at 11343.5,-613.5 h45
  text "LAYOUT BY:" at 12848.5,-613.5 h45
  text "or any information contained therein. TI and/or its licensors do not warrant that this design will meet" at 6329.01,-718 h45
  text ".PRJ_Engineer" at 11393.5,-768.49 h70
  text ".PCB_Layout" at 12899,-768.49 h70
  text "the specifications, will be suitable for your application or fit for any particular purpose, or will operate in" at 6329.01,-830.67 h45
  text ".Layer_Name" at 577,-858.49 h60
  text "ALTIUM DESIGNER VERSION:" at 12848.5,-923.5 h45
  text "an implementation. TI and/or its licensors do not warrant that the design is production worthy. You should" at 6329.01,-943.33 h45
  text "completely validate and test your design implementation to confirm the system functionality for your application." at 6374,-1056 h45
  text ".print_Scale" at 11393.5,-1056.83 h70
  text ".Application_BuildNumber" at 12899,-1056.83 h70
  text "1" at 739.84,-1263.5 h70
  text "2" at 3235.5,-1263.5 h70
  text "3" at 5724.84,-1263.5 h70
  text "4" at 8231.51,-1263.5 h70
  text "5" at 10730.5,-1263.5 h70
  text "6" at 13235.5,-1263.5 h70
M10 Fab Notes:
  drawing of 173 lines, arcs and shapes, not listed
  text "DESIGN INFORMATION" at 12378.02,6201 h60
  text "MIN. TRACK WIDTH:" at 11733.46,6021 h60
  text "8" at 12829.7,6021 h60
  text "MIL" at 12984.46,6021 h60
  text "MIN. CLEARANCE:" at 11733.46,5889 h60
  text "0.2" at 12769.7,5889 h60
  text "mm" at 12984.46,5889 h60
  text "MIN. VIA PAD SIZE:" at 11733.46,5757 h60
  text "24" at 12799.71,5757 h60
  text "MIL" at 12984.46,5757 h60
  text "0.05mm (2MIL)" at 12428.46,5615.29 h60
  text "MINIMUM ANNULAR RING" at 11404.23,5611 h60
  text "EXTERNAL" at 13136.46,5611 h60
  text "PER" at 11604.23,5493 h60
  text "IPC-D-275 CLASS 2 LEVEL C" at 11824.23,5493 h60
  text "MIL, HOLES" at 13312.46,5380.71 h60
  text "+/-" at 12920,5380 h60
  text "+/-" at 13774,5380 h60
  text "REGISTRATION TOLERANCES:" at 11404.23,5375 h60
  text "METAL" at 12604,5375 h60
  text "5" at 13180.2,5375 h60
  text "3" at 14013.2,5375 h60
  text "MIL" at 14129.46,5375 h60
  text "+/-" at 13774,5262 h60
  text "HOLE SIZE TOLERANCE (UNLESS OTHERWISE SPECIFIED):" at 11404.23,5257 h60
  text "3" at 14013.2,5257 h60
  text "MIL" at 14129.46,5257 h60
  text "MATERIAL:" at 11329.46,5047.54 h60
  text "FR-4 High Tg" at 12315.9,4907.21 h60
  text "FR-408" at 11750.46,4898.64 h60
  text "OTHER" at 13238.46,4898.64 h60
  text "X" at 12161,4895 h60
  text "62 MIL (1.6mm) +/-10%" at 12070.56,4735.92 h60
  text "THICKNESS:" at 11404.23,4731.64 h60
  text "X" at 11942.4,4731.64 h60
  text "OTHER" at 13355.46,4731.64 h60
  text "TOLERANCE:" at 11404.23,4573.64 h60
  text "X" at 12243.53,4573.64 h60
  text "ANSI IPC-6012 TYPE 3 CLASS 2" at 12430.48,4573.64 h60
  text "OTHER +/-" at 12430.46,4417.64 h60
  text "BOW & TWIST:" at 11404.23,4260.64 h60
  text "X" at 12243.53,4260.64 h60
  text "ANSI IPC-6012 TYPE 3 CLASS 2" at 12430.48,4260.64 h60
  text "OTHER +/-" at 12430.46,4102.13 h60
  text "DRILLING:" at 11329.46,3963.64 h60
  text "REFERENCE:" at 11404.23,3846.64 h60
  text "X" at 12052.46,3846.64 h60
  text "AS SHOWN" at 12239.46,3846.64 h60
  text "X" at 12953.46,3846.64 h60
  text "NC_DRILL FILES" at 13090.46,3846.64 h60
  text "PTH COPPER THICKNESS:" at 11404.23,3688.64 h60
  text "X" at 12534.46,3688.64 h60
  text "20-30 um" at 12671.46,3688.64 h60
  text "OTHER" at 13388.46,3688.64 h60
  text "BOARD FINISH:" at 11329.46,3529.64 h60
  text "SILKSCREEN:" at 11484.68,3411.64 h60
  text "X" at 12433.46,3411.64 h60
  text "TOP" at 12559.46,3411.64 h60
  text "BOTTOM" at 13070.46,3411.64 h60
  text "SILKSCREEN COLOR:" at 11484.68,3244.64 h60
  text "X" at 12432.42,3244.64 h60
  text "WHITE" at 12559.46,3244.64 h60
  text "OTHER" at 13070.46,3244.64 h60
  text "X" at 12563.42,3085.44 h60
  text "GREEN" at 12690.46,3085.44 h60
  text "OTHER" at 13308.46,3085.44 h60
  text "SOLDER RESIST COLOR:" at 11484.68,3074.64 h60
  text "X" at 12563.42,2915.44 h60
  text "MATTE" at 12690.46,2915.44 h60
  text "SEMI-GLOSS" at 13308,2914.8 h60
  text "IMMERSION GOLD (ENIG)" at 12390.46,2726.92 h60
  text "ENEPIG" at 13728,2723.64 h60
  text "SURFACE FINISH:" at 11329.46,2722.64 h60
  text "X" at 12203.51,2722.64 h60
  text "IMM. TIN/SILVER OR EQUIV" at 11659,2565.64 h60
  text "OTHER" at 13090.46,2565.64 h60
  text "ARRAY/PANEL:" at 11329.46,2386.64 h60
  text "X" at 12189.18,2387.43 h60
  text "CUT AND TRIM PER M1 BOARD OUTLINE" at 12390.46,2382.35 h60
  text "N.C. ROUTE" at 12390.46,2230.64 h60
  text "V. SCORE" at 13256.46,2230.64 h60
  text "CERTIFICATION:" at 11329.46,2093.64 h60
  text "MATERIALS AND WORKMANSHIP FOR ALL PCBS" at 12054.46,2093.64 h60
  text "TO MEET OR EXCEED THE REQUIREMENTS OF:" at 12054.46,1995.64 h60
  text "X" at 11680.96,1859.13 h60
  text "ANSI IPC-A-600F CLASS ->" at 11819.96,1859.13 h60
  text "X" at 13459.02,1859.13 h60
  text "2" at 13577.96,1859.14 h60
  text "1" at 13262.96,1857.64 h60
  text "3" at 13931.96,1857.64 h60
  text "X" at 12495.02,1699.64 h60
  text "RoHS" at 12631.96,1699.64 h60
  text "OTHER" at 13276.36,1699.64 h60
  text "PER ORDER" at 13673.42,1699.64 h60
  text "ALL BOARDS MUST MEET OR EXCEED UL94-V0 REQUIREMENTS." at 11357,1534 h60
  text "PCB MUST BEAR THE UL94V-0 UL REGISTERED MATERIAL ID NUMBER" at 11357,1414 h60
  text "ADDITIONAL REQUIREMENTS:" at 11329.46,1240.64 h60
  text "MICROSECTION:" at 11404.23,1125.64 h60
  text "YES" at 12309.96,1125.64 h60
  text "REQUIRED" at 13171.46,969.49 h60
  text "BARE BOARD ELEC. TEST:" at 11404.23,966.64 h60
  text "NONE" at 12709.96,966.64 h60
  text "X" at 13044.46,966.64 h60
  text "PER ORDER" at 13763.46,966.64 h60
  text ".Layer_Name" at 577,-858.49 h60
M11 Gerber Information:
  lines w10: -292,-930.17 6308,-930.17 ; -292,-726.83 6310,-726.83 ; -292,-523.5 -292,-1133.5 3713,-1133.5 6310,-1133.5 6310,-523.5 -291.5,-523.5 -291.5,-1133.5 1284,-1133.5 ; 2173,-1133.5 2173,-523.5 ; 3440,-726.83 3440,-523.5 ; 4280,-726.83 4280,-523.5 ; 4902,-1140 4902,-937.17
  text "ALL ARTWORK VIEWED FROM TOP SIDE" at -228.5,-655.67 h60
  text "BOARD #:" at 2248,-655.67 h60
  text ".PRJ_Number" at 2793.5,-655.67 h60
  text "REV:" at 3638,-655.67 h60
  text ".PCB_Rev" at 3929.5,-655.67 h60
  text "SVN REV:" at 4476,-655.67 h60
  text ".VersionControl_RevNumber" at 4982,-655.67 h60
  text "LAYER NAME =" at -228.5,-858.49 h60
  text "TID #:" at 2248,-859 h60
  text ".TID" at 2793.5,-859 h60
  text "PLOT NAME =" at -228.5,-1064.34 h60
  text ".plot_File_Name" at 577,-1064.34 h60
  text "GENERATED    :" at 2250,-1064.34 h60
  text ".Print_Date" at 3119.5,-1064.34 h60
  text ".Print_Time" at 3848.5,-1064.34 h60
  text "TEXAS INSTRUMENTS" at 5113,-1064.34 h60
M12 Stackup:
  text ".Layer_Name" at 577,-858.49 h60
M13 Component Bodies Top:
  text ".Layer_Name" at 577,-858.49 h60
M14 Component Bodies Bottom:
  text ".Layer_Name" at 577,-858.49 h60
M15 Courtyards Top:
  text ".Layer_Name" at 577,-858.49 h60
M16 Courtyards Bottom:
  text ".Layer_Name" at 577,-858.49 h60
Drill Drawing:
  circle w10: c296.69,6274.37 r33.33
  lines w10: 263.35,6391.03 330.02,6391.03 330.02,6457.7 263.35,6457.7 263.35,6391.03 ; 263.35,6574.37 296.69,6541.03 330.02,6574.37 296.69,6607.7 263.35,6574.37 ; 263.35,6707.7 280.02,6707.7 280.02,6691.03 313.35,6691.03 313.35,6707.7 330.02,6707.7 330.02,6741.03 313.35,6741.03 313.35,6757.7 280.02,6757.7 280.02,6741.03 263.35,6741.03 263.35,6707.7
  lines w15: 203.56,6196.03 10714.65,6196.03 ; 203.56,6796.03 10714.65,6796.03 ; 754.44,6046.03 754.44,6946.03 ; 1334.29,6046.03 1334.29,6946.03 ; 2423.97,6046.03 2423.97,6946.03 ; 2929.84,6046.03 2929.84,6946.03 ; 3663.65,6046.03 3663.65,6946.03 ; 5163.2,6046.03 5163.2,6946.03 ; 5753.05,6046.03 5753.05,6946.03 ; 6498.84,6046.03 6498.84,6946.03 ; 7148.67,6046.03 7148.67,6946.03 ; 8002.44,6046.03 8002.44,6946.03 ; 9336.04,6046.03 9336.04,6946.03 ; 203.56,6046.03 10714.65,6046.03 10714.65,6946.03 203.56,6946.03 203.56,6046.03
  text "Symbol" at 293.56,6841.03 h72
  text "Count" at 799.44,6841.03 h72
  text "Hole Size" at 1379.29,6841.03 h72
  text "Plated" at 2468.97,6841.03 h72
  text "Hole Type" at 2974.84,6841.03 h72
  text "Drill Layer Pair" at 3708.65,6841.03 h72
  text "Via/Pad" at 5208.2,6841.03 h72
  text "Pad Shape" at 5798.05,6841.03 h72
  text "Template" at 6543.84,6841.03 h72
  text "Description" at 7193.67,6841.03 h72
  text "Hole Tolerance (+)" at 8047.44,6841.03 h72
  text "Hole Tolerance (-)" at 9381.04,6841.03 h72
  text "7" at 799.44,6691.03 h60
  text "7.87mil (0.200mm)" at 1379.29,6691.03 h60
  text "PTH" at 2468.97,6691.03 h60
  text "Round" at 2974.84,6691.03 h60
  text "Top Layer - Bottom Layer" at 3708.65,6691.03 h60
  text "Via" at 5208.2,6691.03 h60
  text "Rounded" at 5798.05,6691.03 h60
  text "(Mixed)" at 6543.84,6691.03 h60
  text "8" at 799.44,6541.03 h60
  text "47.24mil (1.200mm)" at 1379.29,6541.03 h60
  text "PTH" at 2468.97,6541.03 h60
  text "Round" at 2974.84,6541.03 h60
  text "Top Layer - Bottom Layer" at 3708.65,6541.03 h60
  text "Pad" at 5208.2,6541.03 h60
  text "(Mixed)" at 5798.05,6541.03 h60
  text "(Mixed)" at 6543.84,6541.03 h60
  text "9" at 799.44,6391.03 h60
  text "40.00mil (1.016mm)" at 1379.29,6391.03 h60
  text "PTH" at 2468.97,6391.03 h60
  text "Round" at 2974.84,6391.03 h60
  text "Top Layer - Bottom Layer" at 3708.65,6391.03 h60
  text "Pad" at 5208.2,6391.03 h60
  text "Rounded" at 5798.05,6391.03 h60
  text "c203h102" at 6543.84,6391.03 h60
  text "77" at 799.44,6241.03 h60
  text "12.00mil (0.305mm)" at 1379.29,6241.03 h60
  text "PTH" at 2468.97,6241.03 h60
  text "Round" at 2974.84,6241.03 h60
  text "Top Layer - Bottom Layer" at 3708.65,6241.03 h60
  text "Via" at 5208.2,6241.03 h60
  text "Rounded" at 5798.05,6241.03 h60
  text "(Mixed)" at 6543.84,6241.03 h60
  text "101 Total" at 799.44,6091.03 h60
  text ".Layer_Name" at 577,-858.49 h60
M17 Embedded Cavity:
  text ".Layer_Name" at 577,-858.49 h60
M18 Embedded Assembly:
  text ".Layer_Name" at 577,-858.49 h60
M19 Embedded Keepout:
  text ".Layer_Name" at 577,-858.49 h60

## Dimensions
0,-400 to 1000,-400 on M2 Board Dimensions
